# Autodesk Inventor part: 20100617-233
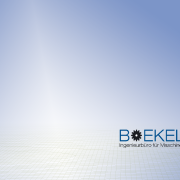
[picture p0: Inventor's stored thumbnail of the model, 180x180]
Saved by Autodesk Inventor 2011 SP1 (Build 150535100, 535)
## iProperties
Created: 2010-11
Part Number: 20100617-233
Document SubType Name: Modeling
Designer: Boekels
Density: 7.85 g/cm^3
Material: 1.0715
Mass: 322.169 g
Surface Area: 255.817 cm^2
Volume: 41.0407 cm^3
Description: Mitnehmer
Masse: 322 g
Rohmasse: 88,8mm x 83,7mm x 67,7mm
Part Number Kunde: 20100617-233
Halbzeug: Rund 100 DIN 1013
Oberfläche: Fe/Zn 8c-B
Tätigkeit: fertigen
Author: Boekels
Title: Mitnehmer
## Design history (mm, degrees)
node "20100617-094 - Gehäuse - Wellengelenk" dims "d0" = 10
sketch "Skizze19"
  geometry: L1 (45.27, 8.164)-(35.428, 6.389); A1 r 41 centre (0, 0) between (40.349, 7.277) and (41, 0); 2 further points
  constraints: 2 end point, 1 centre point, 1 horizontal alignment, 1 point on circle
hole "Hole1" sketch "Skizze19" diameter "d1" = 6.6; stored, may be unused: countersink angle "d5" = 90 deg, drill point angle "d7" = 118 deg; dims "d2" = 6, "d3" = 4, "d4" = 2, "d6" = 8
pattern_circular "Runde Anordnung1" dims angle "d9" = 360 deg
sketch "Skizze2"
  geometry: L1 (11.8, 3)-(0, 3); L2 (0, 3)-(0, -3); L3 (0, -3)-(11.8, -3); L4 (11.8, -3)-(11.8, 3); C1 r 9 at (0, 0) reference; 2 further points
  constraints: 8 end point, 2 parallel, 1 coincident, 1 horizontal, 1 midpoint, 1 perpendicular
  dimensions: "d11" = 18 diameter of C1 (derived); "d12" = 6 distance between parallel lines of L3 L1; "d13" = 2.8 distance edge to line of C1 L4
extrude "Extrusion1" cut sketch "Skizze2" stored distance "d14" = 10; taper "d15" = 0 deg
node "Mittelebene"
workaxis "Arbeitsachse1"
sketch "Skizze3"
  geometry: L1 (-34.2, 41)-(-34.2, 16) reference; L2 (-34.2, 16)-(-23.7, 16); L3 (-23.7, 16)-(-23.7, 36); L4 (-23.7, 36)-(-34.2, 36); L5 (-34.2, 36)-(-34.2, 16); L6 (-32.5, 41)-(-25.9, 41) reference; L7 (11.8, 259.552)-(11.8, -211.268) reference; 2 further points
  constraints: 8 end point, 2 parallel, 1 horizontal, 1 midpoint, 1 perpendicular
  dimensions: "d24" = 5 distance from line of L1.start L4; "d25" = 5.5 distance from line of L3 point (-29.2, 41)
revolve "Umdrehung1" sketch "Skizze3" stored, may be unused: angle "d26" = 90 deg
chamfer "Fase1" distance "d16" = 1; stored, may be unused: second distance "d17" = 2, angle "d18" = 45 deg
fillet "Rundung1" dims "d19" = 2
fillet "Rundung2" dims "d20" = 2
chamfer "Fase2" distance "d21" = 1; stored, may be unused: second distance "d22" = 2, angle "d23" = 30 deg
workplane "Arbeitsebene2"
feature "Trennen1"
chamfer "Fase3" distance "d27" = 1; stored, may be unused: second distance "d28" = 2, angle "d29" = 45 deg
workplane "Arbeitsebene3"
node "Volumenkörpern"
node "Oberflächenkörpern"
feature "20100617-233::20100617-094 - Gehäuse - Wellengelenk" dims "d0" = 10
tag "Bezeichnung1"
node "Volumenkörper1"
other parameters: "d30" = -8, "d31" = 0, "d32" = 0, "d33" = 0, "d34" = 0, "d35" = 0, "d36" = 0
